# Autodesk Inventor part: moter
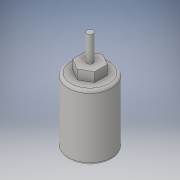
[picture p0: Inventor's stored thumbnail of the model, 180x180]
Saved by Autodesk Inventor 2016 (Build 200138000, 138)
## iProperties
Created: 2020-03
Part Number: moter
Material: Generic
Document SubType Name: Modeling
Designer: merlin
Density: 1 g/cm^3
Appearance: Default
Author: merlin
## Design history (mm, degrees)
sketch "Sketch1"
  geometry: C1 r 25.4 at (0, 0); 1 further point
  constraints: 1 centre point, 1 coincident
  dimensions: "d0" = 50.8 diameter of C1
extrude "Extrusion1" new body sketch "Sketch1" distance "d1" = 76.2; taper "d2" = 0 deg
sketch "Sketch2"
  geometry: L1 (0, 14.809)-(12.825, 7.405); L2 (12.825, 7.405)-(12.825, -7.405); L3 (12.825, -7.405)-(0, -14.809); L4 (0, -14.809)-(-12.825, -7.405); L5 (-12.825, -7.405)-(-12.825, 7.405); L6 (-12.825, 7.405)-(0, 14.809); 2 further points
  constraints: 12 end point, 1 coincident, 13 other
extrude "Extrusion2" join sketch "Sketch2" distance "d3" = 11; taper "d4" = 0 deg
sketch "Sketch3"
  geometry: C1 r 3.55 at (0, 0); 1 further point
  constraints: 1 centre point, 1 coincident
extrude "Extrusion3" join sketch "Sketch3" distance "d5" = 30; taper "d6" = 0 deg
fillet "Fillet1" dims "d7" = 3.175
fillet "Fillet2" dims "d8" = 3.175
body "Solid1"
